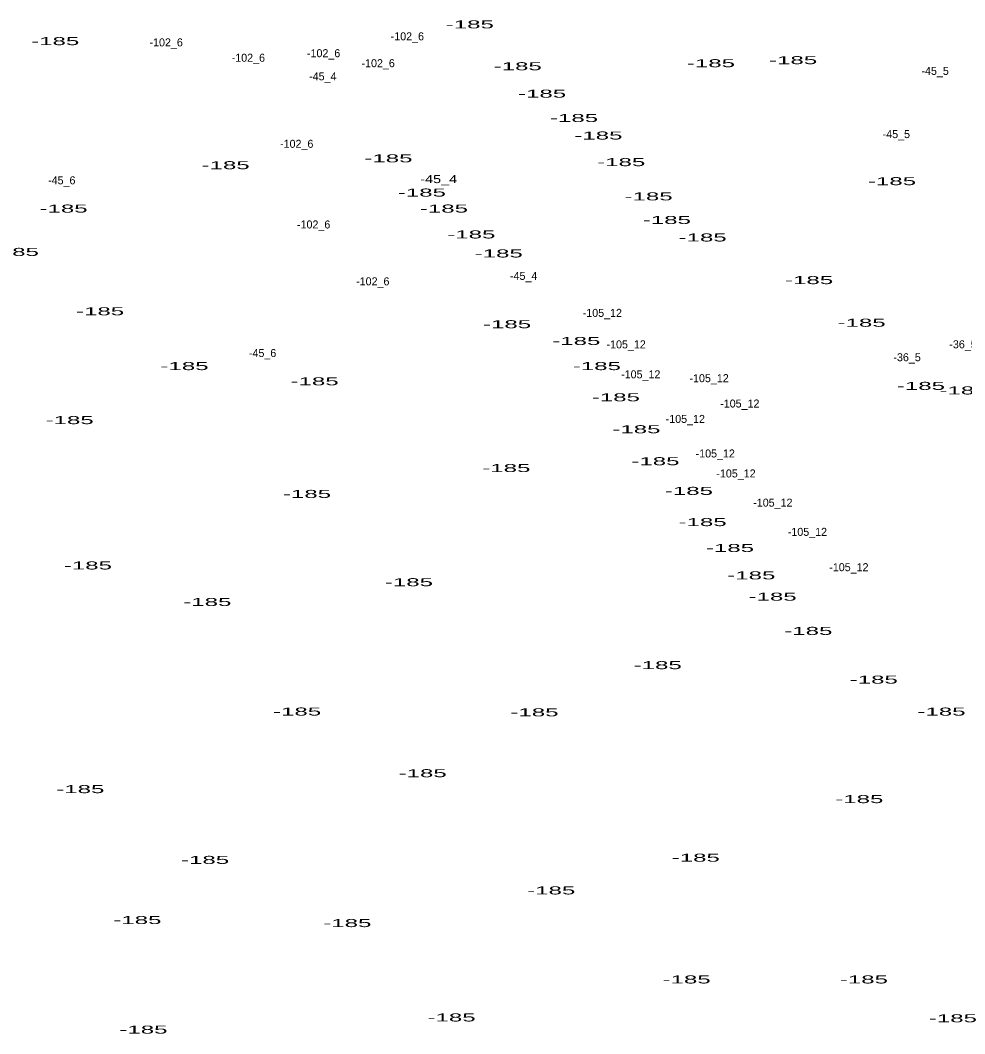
# Model space of a CAD drawing. Extents: x -658595 to -655205, y -1004347 to -1000147.
# Drawn here: x -657461 to -656989, y -1001709 to -1001203 of the extents above; entities that cross this region are included whole.
import ezdxf
from ezdxf.enums import TextEntityAlignment as Align

# ---------------------------------------------------------------- set-up
doc = ezdxf.new("R2010")
doc.units = 0
doc.header["$LTSCALE"] = 1.6
doc.layers.add('24', color=7, linetype='Continuous')

msp = doc.modelspace()

# ---------------------------------------------------------------- texts
at = {"layer": '24'}
for s, width, p in [('-185', 2.25, (-657236.071, -1001206.79)), ('-185', 2.25, (-657443.371, -1001215.17)), ('-185', 2.25, (-657212.101, -1001227.72)), ('-185', 2.25, (-657115.501, -1001226.2)), ('-185', 2.25, (-657074.431, -1001224.68)), ('-185', 2.25, (-657199.931, -1001241.42)), ('-185', 2.25, (-657183.961, -1001253.6)), ('-185', 2.25, (-657171.781, -1001262.35)), ('-185', 2.25, (-657276.761, -1001273.76)), ('-185', 2.25, (-657358.161, -1001277.19)), ('-185', 2.25, (-657160.371, -1001275.66)), ('-45_4', 1.35, (-657251.64, -1001284.15)), ('-185', 2.25, (-657024.981, -1001285.18)), ('-185', 2.25, (-657260.031, -1001290.88)), ('-185', 2.25, (-657146.681, -1001292.79)), ('-185', 2.25, (-657439.191, -1001298.88)), ('-185', 2.25, (-657249.001, -1001298.88)), ('-185', 2.25, (-657137.551, -1001304.58)), ('-185', 2.25, (-657235.311, -1001311.81)), ('-185', 2.25, (-657119.671, -1001313.33)), ('-185', 2.25, (-657463.531, -1001320.56)), ('-185', 2.25, (-657221.611, -1001321.32)), ('-185', 2.25, (-657066.441, -1001334.65)), ('-185', 2.25, (-657420.931, -1001350.24)), ('-185', 2.25, (-657040.191, -1001355.96)), ('-185', 2.25, (-657217.441, -1001356.71)), ('-185', 2.25, (-657182.821, -1001365.08)), ('-185', 2.25, (-657378.711, -1001377.64)), ('-185', 2.25, (-657172.551, -1001377.64)), ('-185', 2.25, (-657313.671, -1001385.25)), ('-185', 2.25, (-657010.521, -1001387.54)), ('-185', 2.25, (-656989.221, -1001389.82)), ('-185', 2.25, (-657163.041, -1001393.24)), ('-185', 2.25, (-657436.141, -1001404.66)), ('-185', 2.25, (-657152.771, -1001409.22)), ('-185', 2.25, (-657143.261, -1001425.2)), ('-185', 2.25, (-657217.811, -1001428.62)), ('-185', 2.25, (-657317.471, -1001441.56)), ('-185', 2.25, (-657126.521, -1001440.04)), ('-185', 2.25, (-657119.681, -1001455.64)), ('-185', 2.25, (-657105.981, -1001468.58)), ('-185', 2.25, (-657427.021, -1001477.33)), ('-185', 2.25, (-657095.331, -1001482.28)), ('-185', 2.25, (-657266.501, -1001485.7)), ('-185', 2.25, (-657084.681, -1001492.93)), ('-185', 2.25, (-657367.301, -1001495.59)), ('-185', 2.25, (-657066.811, -1001510.05)), ('-185', 2.25, (-657142.121, -1001527.17)), ('-185', 2.25, (-657034.101, -1001534.4)), ('-185', 2.25, (-657322.411, -1001550.38)), ('-185', 2.25, (-657203.741, -1001550.76)), ('-185', 2.25, (-657000.241, -1001550.39)), ('-185', 2.25, (-657259.651, -1001581.2)), ('-185', 2.25, (-657430.811, -1001589.16)), ('-185', 2.25, (-657041.331, -1001594.14)), ('-185', 2.25, (-657368.431, -1001624.55)), ('-185', 2.25, (-657123.101, -1001623.44)), ('-185', 2.25, (-657195.371, -1001639.8)), ('-185', 2.25, (-657402.281, -1001654.61)), ('-185', 2.25, (-657297.301, -1001656.13)), ('-185', 2.25, (-657127.671, -1001684.32)), ('-185', 2.25, (-657039.041, -1001684.32)), ('-185', 2.25, (-657245.191, -1001703.32)), ('-185', 2.25, (-656994.541, -1001703.73)), ('-185', 2.25, (-657399.241, -1001709.4))]:
    msp.add_text(s, height=4, dxfattribs=dict(at, width=width)).set_placement(p, align=Align.CENTER)
for s, p in [('-102_6', (-657267.306, -1001212.75)), ('-102_6', (-657387.886, -1001215.78)), ('-102_6', (-657346.796, -1001223.47)), ('-102_6', (-657309.166, -1001221.2)), ('-102_6', (-657281.896, -1001226.19)), ('-45_4', (-657309.561, -1001232.76)), ('-45_5', (-657003.417, -1001230.05)), ('-45_5', (-657022.817, -1001261.64)), ('-102_6', (-657322.606, -1001266.49)), ('-45_6', (-657440.082, -1001284.75)), ('-102_6', (-657314.156, -1001306.83)), ('-102_6', (-657284.586, -1001335.26)), ('-45_4', (-657209.151, -1001332.53)), ('-105_12', (-657169.813, -1001351.03)), ('-45_6', (-657339.672, -1001371.12)), ('-105_12', (-657157.903, -1001366.78)), ('-36_5', (-656989.488, -1001366.74)), ('-36_5', (-657017.448, -1001373.21)), ('-105_12', (-657150.603, -1001381.76)), ('-105_12', (-657116.433, -1001383.68)), ('-105_12', (-657101.073, -1001396.36)), ('-105_12', (-657128.333, -1001404.04)), ('-105_12', (-657113.363, -1001421.33)), ('-105_12', (-657102.993, -1001431.32)), ('-105_12', (-657084.553, -1001445.92)), ('-105_12', (-657067.273, -1001460.52)), ('-105_12', (-657046.543, -1001478.19))]:
    msp.add_text(s, height=4, dxfattribs=at).set_placement(p, align=Align.CENTER)

doc.saveas('drawing.dxf')
